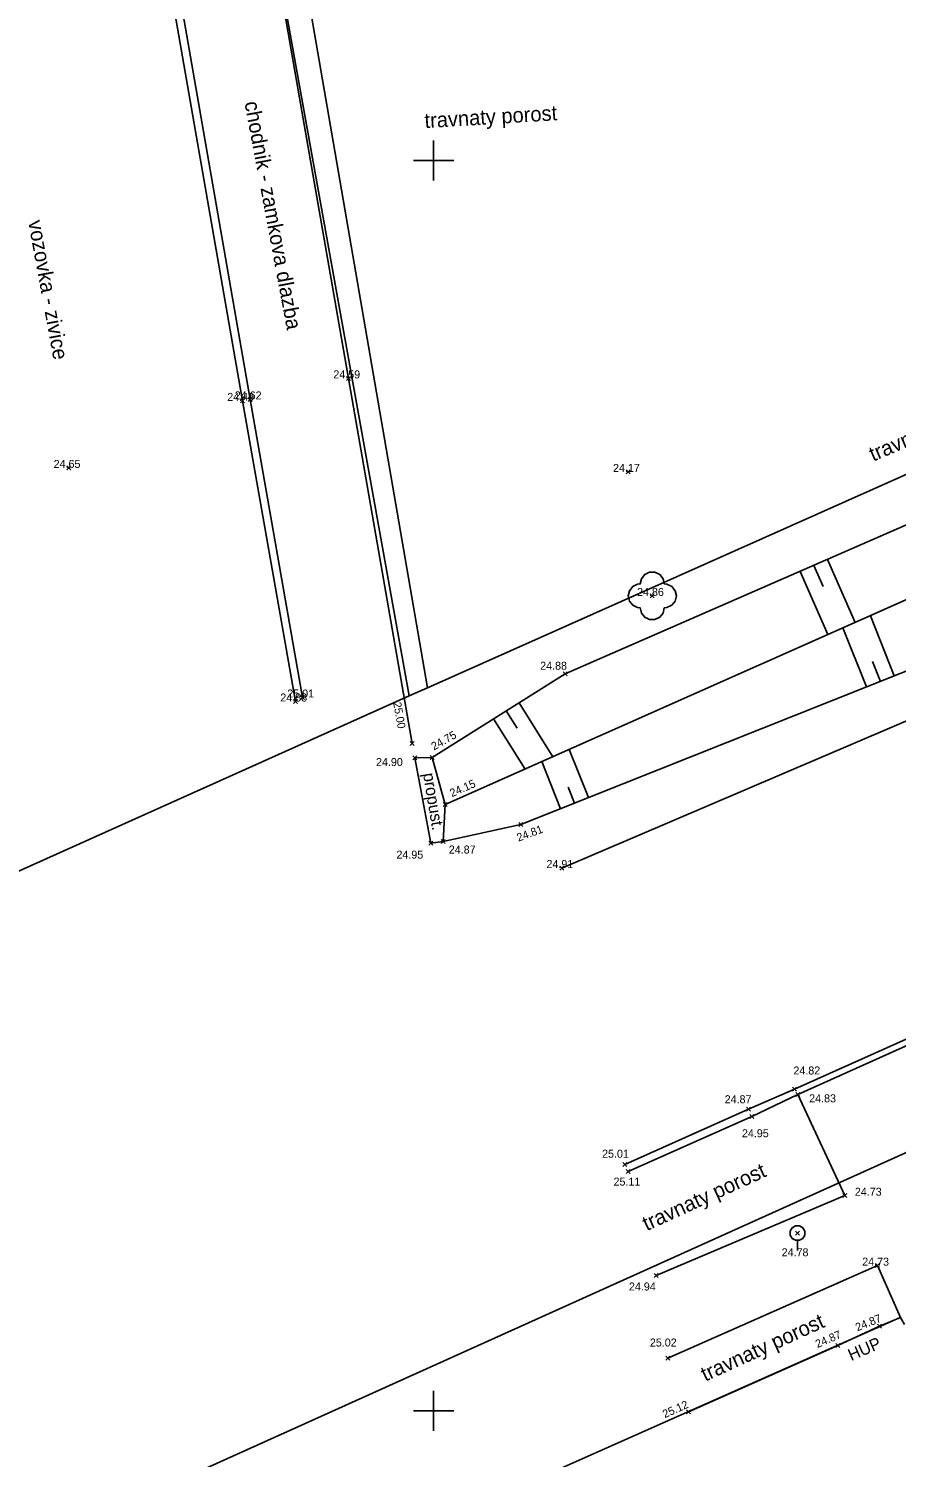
# Model space of a CAD drawing. Extents: x -772300 to -772183, y -1034101 to -1034019.
# Drawn here: x -772258.1 to -772240.75, y -1034075.93 to -1034047.37 of the extents above; entities that cross this region are included whole.
import ezdxf

# ---------------------------------------------------------------- set-up
doc = ezdxf.new("R2010")
doc.units = 0
for name, color, linetype in [('body', 7, 'Continuous'), ('HUP_el', 7, 'Continuous'), ('kanalizace', 7, 'Continuous'), ('KM_hranice', 7, 'Continuous'), ('mistni_popis', 7, 'Continuous'), ('oddeleni_ploch', 7, 'Continuous'), ('oploceni', 7, 'Continuous'), ('souradnicova_sit', 7, 'Continuous'), ('stromy_kere', 7, 'Continuous'), ('svah_srafy_vrstevnice', 7, 'Continuous'), ('svahy', 7, 'Continuous'), ('vyskove_koty', 7, 'Continuous'), ('zídky', 7, 'Continuous')]:
    doc.layers.add(name, color=color, linetype=linetype)

msp = doc.modelspace()

# ---------------------------------------------------------------- linework, layer by layer
at = {"layer": 'body'}
for p, q in [((-772251.66, -1034054.4), (-772251.74, -1034054.32)), ((-772251.74, -1034054.4), (-772251.66, -1034054.32)), ((-772253.78, -1034054.85), (-772253.86, -1034054.77)), ((-772253.86, -1034054.85), (-772253.78, -1034054.77)), ((-772253.63, -1034054.82), (-772253.71, -1034054.74)), ((-772253.71, -1034054.82), (-772253.63, -1034054.74)), ((-772257.25, -1034056.19), (-772257.33, -1034056.11)), ((-772257.33, -1034056.19), (-772257.25, -1034056.11)), ((-772246.07, -1034056.27), (-772246.15, -1034056.19)), ((-772246.15, -1034056.27), (-772246.07, -1034056.19)), ((-772245.59, -1034058.75), (-772245.67, -1034058.67)), ((-772245.67, -1034058.75), (-772245.59, -1034058.67)), ((-772247.33, -1034060.31), (-772247.41, -1034060.23)), ((-772247.41, -1034060.31), (-772247.33, -1034060.23)), ((-772252.58, -1034060.78), (-772252.66, -1034060.7)), ((-772252.66, -1034060.78), (-772252.58, -1034060.7)), ((-772252.72, -1034060.86), (-772252.8, -1034060.78)), ((-772252.8, -1034060.86), (-772252.72, -1034060.78)), ((-772250.39, -1034061.7), (-772250.47, -1034061.62)), ((-772250.47, -1034061.7), (-772250.39, -1034061.62)), ((-772250.337, -1034061.986), (-772250.417, -1034061.906)), ((-772250.417, -1034061.986), (-772250.337, -1034061.906)), ((-772249.99, -1034061.98), (-772250.07, -1034061.9)), ((-772250.07, -1034061.98), (-772249.99, -1034061.9)), ((-772249.73, -1034062.92), (-772249.81, -1034062.84)), ((-772249.81, -1034062.92), (-772249.73, -1034062.84)), ((-772248.22, -1034063.32), (-772248.3, -1034063.24)), ((-772248.3, -1034063.32), (-772248.22, -1034063.24)), ((-772250.017, -1034063.696), (-772250.097, -1034063.616)), ((-772250.097, -1034063.696), (-772250.017, -1034063.616)), ((-772249.77, -1034063.66), (-772249.85, -1034063.58)), ((-772249.85, -1034063.66), (-772249.77, -1034063.58)), ((-772247.4, -1034064.19), (-772247.48, -1034064.11)), ((-772247.48, -1034064.19), (-772247.4, -1034064.11)), ((-772242.75, -1034068.61), (-772242.83, -1034068.53)), ((-772242.83, -1034068.61), (-772242.75, -1034068.53)), ((-772242.68, -1034068.72), (-772242.76, -1034068.64)), ((-772242.76, -1034068.72), (-772242.68, -1034068.64)), ((-772243.67, -1034069.01), (-772243.75, -1034068.93)), ((-772243.75, -1034069.01), (-772243.67, -1034068.93)), ((-772243.6, -1034069.16), (-772243.68, -1034069.08)), ((-772243.68, -1034069.16), (-772243.6, -1034069.08)), ((-772246.14, -1034070.12), (-772246.22, -1034070.04)), ((-772246.22, -1034070.12), (-772246.14, -1034070.04)), ((-772246.07, -1034070.26), (-772246.15, -1034070.18)), ((-772246.15, -1034070.26), (-772246.07, -1034070.18)), ((-772241.74, -1034070.74), (-772241.82, -1034070.66)), ((-772241.82, -1034070.74), (-772241.74, -1034070.66)), ((-772242.69, -1034071.49), (-772242.77, -1034071.41)), ((-772242.77, -1034071.49), (-772242.69, -1034071.41)), ((-772241.09, -1034072.14), (-772241.17, -1034072.06)), ((-772241.17, -1034072.14), (-772241.09, -1034072.06)), ((-772245.51, -1034072.34), (-772245.59, -1034072.26)), ((-772245.59, -1034072.34), (-772245.51, -1034072.26)), ((-772241.05, -1034073.35), (-772241.13, -1034073.27)), ((-772241.13, -1034073.35), (-772241.05, -1034073.27)), ((-772245.28, -1034073.99), (-772245.36, -1034073.91)), ((-772245.36, -1034073.99), (-772245.28, -1034073.91)), ((-772241.88, -1034073.74), (-772241.96, -1034073.66)), ((-772241.96, -1034073.74), (-772241.88, -1034073.66)), ((-772244.87, -1034075.06), (-772244.95, -1034074.98)), ((-772244.95, -1034075.06), (-772244.87, -1034074.98))]:
    msp.add_line(p, q, dxfattribs=at)
at = {"layer": 'HUP_el'}
msp.add_line((-772241.92, -1034073.7), (-772241.09, -1034073.31), dxfattribs=at)
at = {"layer": 'kanalizace'}
msp.add_line((-772242.738, -1034071.45), (-772242.718, -1034071.45), dxfattribs=at)
msp.add_lwpolyline([(-772242.73, -1034071.594), (-772242.768, -1034071.594), (-772242.836, -1034071.556), (-772242.874, -1034071.488), (-772242.874, -1034071.41), (-772242.836, -1034071.342), (-772242.768, -1034071.304), (-772242.69, -1034071.304), (-772242.622, -1034071.342), (-772242.584, -1034071.41), (-772242.584, -1034071.488), (-772242.622, -1034071.556), (-772242.69, -1034071.594), (-772242.728, -1034071.594), (-772242.728, -1034071.8)], dxfattribs=at)
at = {"layer": 'KM_hranice'}
for p, q in [((-772258.001, -1034018.905), (-772250.49, -1034060.71)), ((-772250.12, -1034060.55), (-772257.314, -1034018.905)), ((-772234.61, -1034053.62), (-772250.12, -1034060.55)), ((-772250.49, -1034060.71), (-772258.72, -1034064.4)), ((-772250.12, -1034060.55), (-772250.49, -1034060.71)), ((-772237.52, -1034068.47), (-772299.808, -1034096.549)), ((-772276.27, -1034088.94), (-772240.68, -1034073.14))]:
    msp.add_line(p, q, dxfattribs=at)
at = {"layer": 'oddeleni_ploch'}
for p, q in [((-772251.7, -1034054.36), (-772250.43, -1034061.66)), ((-772253.82, -1034054.81), (-772252.76, -1034060.82)), ((-772253.67, -1034054.78), (-772252.62, -1034060.74)), ((-772247.44, -1034064.15), (-772238.22, -1034060.21)), ((-772246.18, -1034070.08), (-772243.71, -1034068.97)), ((-772246.11, -1034070.22), (-772243.64, -1034069.12)), ((-772245.55, -1034072.3), (-772241.78, -1034070.7)), ((-772245.32, -1034073.95), (-772241.13, -1034072.1)), ((-772241.13, -1034072.1), (-772240.67, -1034073.14))]:
    msp.add_line(p, q, dxfattribs=at)
for points in [[(-772251.7, -1034054.36), (-772253.03, -1034046.76), (-772254.33, -1034039.57)], [(-772253.82, -1034054.81), (-772255.19, -1034046.94), (-772256.44, -1034040.05)], [(-772253.67, -1034054.78), (-772255.04, -1034046.9), (-772256.3, -1034040.02)], [(-772243.71, -1034068.97), (-772242.79, -1034068.57), (-772238.01, -1034066.43), (-772233.58, -1034064.44), (-772232.34, -1034063.87), (-772222, -1034059.3)], [(-772242.72, -1034068.68), (-772237.96, -1034066.54), (-772233.5, -1034064.54), (-772232.6, -1034066.64), (-772220.78, -1034061.42)], [(-772243.64, -1034069.12), (-772242.72, -1034068.68), (-772241.78, -1034070.7)]]:
    msp.add_lwpolyline(points, dxfattribs=at)
at = {"layer": 'oploceni'}
msp.add_line((-772244.91, -1034075.02), (-772241.92, -1034073.7), dxfattribs=at)
msp.add_lwpolyline([(-772241.09, -1034073.31), (-772240.67, -1034073.14), (-772240.59, -1034073.28)], dxfattribs=at)
at = {"layer": 'souradnicova_sit'}
for p, q in [((-772250, -1034049.6), (-772250, -1034050.4)), ((-772250.4, -1034050), (-772249.6, -1034050)), ((-772250, -1034074.6), (-772250, -1034075.4)), ((-772250.4, -1034075), (-772249.6, -1034075))]:
    msp.add_line(p, q, dxfattribs=at)
at = {"layer": 'stromy_kere'}
msp.add_lwpolyline([(-772245.15, -1034058.71), (-772245.174, -1034058.813), (-772245.241, -1034058.897), (-772245.337, -1034058.943), (-772245.39, -1034058.95), (-772245.414, -1034059.053), (-772245.481, -1034059.137), (-772245.577, -1034059.183), (-772245.685, -1034059.183), (-772245.781, -1034059.137), (-772245.848, -1034059.053), (-772245.872, -1034058.95), (-772245.925, -1034058.943), (-772246.021, -1034058.897), (-772246.088, -1034058.813), (-772246.112, -1034058.71), (-772246.088, -1034058.607), (-772246.021, -1034058.523), (-772245.925, -1034058.477), (-772245.872, -1034058.47), (-772245.848, -1034058.367), (-772245.781, -1034058.283), (-772245.685, -1034058.237), (-772245.577, -1034058.237), (-772245.481, -1034058.283), (-772245.414, -1034058.367), (-772245.39, -1034058.47), (-772245.337, -1034058.477), (-772245.241, -1034058.523), (-772245.174, -1034058.607)], close=True, dxfattribs=at)
msp.add_lwpolyline([(-772245.642, -1034058.71), (-772245.63, -1034058.71), (-772245.618, -1034058.71)], dxfattribs=at)
at = {"layer": 'svah_srafy_vrstevnice'}
for p, q in [((-772242.401, -1034058.098), (-772242.217, -1034058.519)), ((-772242.126, -1034057.978), (-772241.575, -1034059.24)), ((-772242.676, -1034058.219), (-772242.123, -1034059.483)), ((-772240.794, -1034060.306), (-772241.272, -1034059.105)), ((-772241.351, -1034060.528), (-772241.821, -1034059.349)), ((-772241.073, -1034060.417), (-772241.23, -1034060.021)), ((-772248.548, -1034061.01), (-772248.331, -1034061.355)), ((-772248.294, -1034060.85), (-772247.619, -1034061.925)), ((-772248.802, -1034061.169), (-772248.173, -1034062.171)), ((-772246.906, -1034062.741), (-772247.289, -1034061.778)), ((-772247.463, -1034062.963), (-772247.838, -1034062.022)), ((-772247.184, -1034062.852), (-772247.311, -1034062.535))]:
    msp.add_line(p, q, dxfattribs=at)
at = {"layer": 'svahy'}
for points in [[(-772226.58, -1034051.24), (-772237.76, -1034056.07), (-772247.37, -1034060.27), (-772250.03, -1034061.94)], [(-772226.27, -1034052.57), (-772237.23, -1034057.31), (-772249.77, -1034062.88)], [(-772225.85, -1034053.56), (-772236.56, -1034058.62), (-772248.26, -1034063.28), (-772249.81, -1034063.62)]]:
    msp.add_lwpolyline(points, dxfattribs=at)
at = {"layer": 'zídky'}
msp.add_line((-772250.377, -1034061.946), (-772250.057, -1034063.656), dxfattribs=at)
msp.add_lwpolyline([(-772250.057, -1034063.656), (-772249.81, -1034063.62), (-772249.77, -1034062.88), (-772250.03, -1034061.94), (-772250.377, -1034061.946)], dxfattribs=at)

# ---------------------------------------------------------------- texts
at = {"layer": 'mistni_popis'}
for s, height, rotation, p in [('chodnik - zamkova dlazba', 0.3, 280.5774, (-772253.782, -1034048.845)), ('travnaty porost', 0.3, 3.4377, (-772250.174, -1034049.356)), ('vozovka - zivice', 0.3, 280.4055, (-772258.105, -1034051.222)), ('travnaty porost', 0.3, 23.2048, (-772241.217, -1034056.026)), ('propust.', 0.24, 279.3169, (-772250.214, -1034062.265)), ('travnaty porost', 0.3, 24.5799, (-772245.742, -1034071.412)), ('travnaty porost', 0.3, 24.5799, (-772244.573, -1034074.422)), ('HUP', 0.24, 23.4913, (-772241.655, -1034074.01))]:
    msp.add_text(s, height=height, rotation=rotation, dxfattribs=at).set_placement(p)
at = {"layer": 'vyskove_koty'}
for s, p in [('24.59', (-772252.005, -1034054.36)), ('24.49', (-772254.125, -1034054.81)), ('24.62', (-772253.975, -1034054.78)), ('24.65', (-772257.595, -1034056.15)), ('24.17', (-772246.415, -1034056.23)), ('24.86', (-772245.935, -1034058.71)), ('24.88', (-772247.871, -1034060.185)), ('24.88', (-772253.065, -1034060.82)), ('25.01', (-772252.925, -1034060.74)), ('24.90', (-772251.152, -1034062.111)), ('24.95', (-772250.744, -1034063.962)), ('24.87', (-772249.697, -1034063.86)), ('24.91', (-772247.745, -1034064.15)), ('24.82', (-772242.81, -1034068.278)), ('24.87', (-772244.184, -1034068.853)), ('24.83', (-772242.495, -1034068.835)), ('24.95', (-772243.839, -1034069.533)), ('25.01', (-772246.634, -1034069.942)), ('25.11', (-772246.405, -1034070.5)), ('24.73', (-772241.582, -1034070.702)), ('24.78', (-772243.045, -1034071.913)), ('24.73', (-772241.435, -1034072.1)), ('24.94', (-772246.097, -1034072.597)), ('25.02', (-772245.679, -1034073.717))]:
    msp.add_text(s, height=0.16, dxfattribs=at).set_placement(p)
for s, rotation, p in [('25.00', 280.291, (-772250.81, -1034060.846)), ('24.75', 29.5646, (-772249.992, -1034061.8)), ('24.15', 23.6632, (-772249.635, -1034062.734)), ('24.81', 20.4546, (-772248.304, -1034063.623)), ('24.87', 22.2308, (-772241.532, -1034073.415)), ('24.87', 23.2621, (-772242.33, -1034073.749)), ('25.12', 24.0642, (-772245.381, -1034075.151))]:
    msp.add_text(s, height=0.16, rotation=rotation, dxfattribs=at).set_placement(p)

doc.saveas('drawing.dxf')
